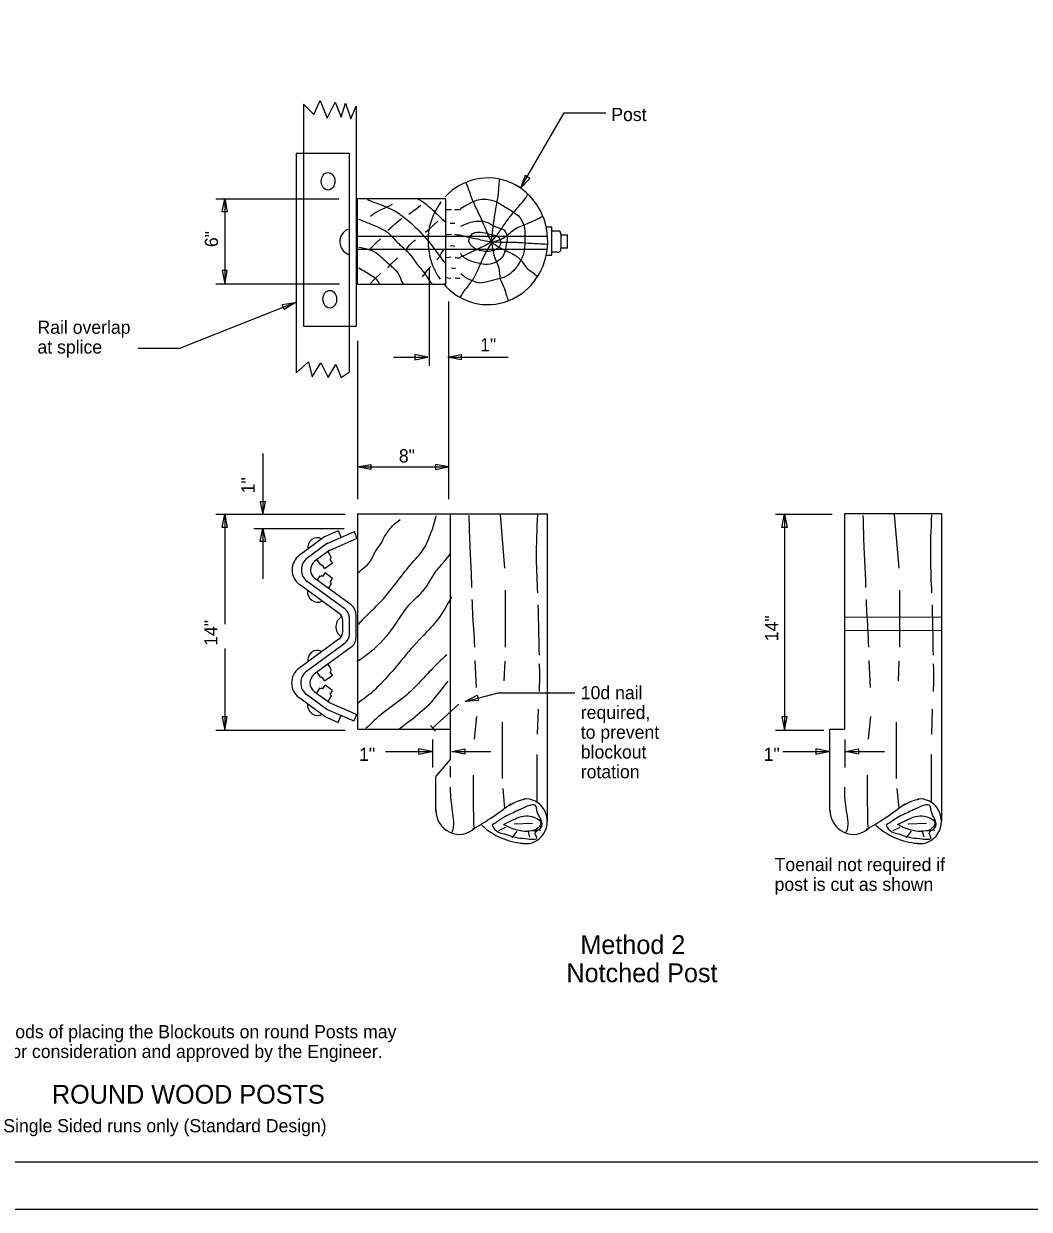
# Model space of a CAD drawing. Extents: x 0 to 34, y 0 to 22.
# Drawn here: x 8.69 to 19.37, y 0 to 12.6 of the extents above; entities that cross this region are included whole.
import ezdxf

# ---------------------------------------------------------------- set-up
doc = ezdxf.new("R2010")
doc.units = 0
for name, color, linetype in [('SH_Border', 7, 'Continuous'), ('SH_Cut_Line', 7, 'Continuous'), ('ST_Details', 7, 'Continuous'), ('ST_Text', 7, 'Continuous')]:
    doc.layers.add(name, color=color, linetype=linetype)

msp = doc.modelspace()

# ---------------------------------------------------------------- linework, layer by layer
at = {"layer": 'SH_Border'}
msp.add_lwpolyline([(1.5, 21.5), (33.5, 21.5), (33.5, 0.5), (1.5, 0.5)], close=True, dxfattribs=at)
at = {"layer": 'SH_Cut_Line'}
msp.add_lwpolyline([(0, 0), (34, 0), (34, 22), (0, 22)], close=True, dxfattribs=at)
at = {"layer": 'ST_Details'}
for p, q in [((11.658, 11.741), (11.658, 11.227)), ((12.218, 11.721), (12.218, 9.383)), ((11.583, 11.221), (11.583, 8.885)), ((11.583, 11.221), (12.143, 11.221)), ((11.658, 11.221), (11.658, 9.383)), ((12.143, 11.221), (12.143, 8.895)), ((12.232, 10.739), (13.171, 10.739)), ((12.232, 9.829), (12.232, 10.739)), ((13.17, 9.829), (13.17, 10.739)), ((13.216, 10.476), (13.266, 10.478)), ((12.225, 10.339), (14.248, 10.339)), ((13.174, 10.357), (13.23, 10.361)), ((14.239, 10.437), (14.299, 10.437)), ((14.251, 10.342), (14.251, 10.342)), ((14.299, 10.136), (14.299, 10.437)), ((14.299, 10.394), (14.367, 10.394)), ((14.393, 10.36), (14.394, 10.206)), ((14.393, 10.353), (14.464, 10.353)), ((14.464, 10.213), (14.464, 10.353)), ((14.394, 10.213), (14.464, 10.213)), ((12.225, 10.2), (14.248, 10.2)), ((13.174, 10.111), (13.228, 10.12)), ((14.239, 10.136), (14.299, 10.136)), ((14.299, 10.17), (14.358, 10.17)), ((12.232, 9.829), (13.17, 9.829)), ((13.17, 9.899), (13.226, 9.892)), ((11.658, 9.383), (12.143, 9.383)), ((12.143, 9.383), (12.218, 9.383)), ((12.232, 7.389), (12.232, 5.099)), ((12.232, 7.389), (14.252, 7.389)), ((13.218, 7.389), (13.218, 4.777)), ((13.748, 7.383), (13.795, 6.81)), ((14.252, 4.122), (14.252, 7.389)), ((17.405, 7.389), (17.405, 5.099)), ((18.439, 7.389), (17.405, 7.389)), ((17.935, 7.383), (17.982, 6.81)), ((18.439, 4.122), (18.439, 7.389)), ((11.887, 7.147), (12.031, 7.21)), ((11.912, 7.074), (12.201, 7.201)), ((12.059, 7.14), (12.031, 7.209)), ((12.227, 7.13), (12.2, 7.2)), ((11.887, 7.147), (11.614, 6.947)), ((11.914, 7.076), (11.684, 6.907)), ((11.941, 7.004), (12.231, 7.13)), ((11.94, 7.003), (11.773, 6.881)), ((11.951, 6.936), (11.921, 6.984)), ((11.835, 6.854), (11.806, 6.9)), ((11.884, 6.807), (11.861, 6.844)), ((11.884, 6.808), (11.966, 6.866)), ((11.966, 6.866), (11.943, 6.902)), ((12.164, 6.42), (11.78, 6.7)), ((11.805, 6.681), (11.837, 6.731)), ((11.865, 6.722), (11.89, 6.76)), ((11.969, 6.703), (11.89, 6.76)), ((11.944, 6.664), (11.968, 6.702)), ((12.038, 6.33), (11.615, 6.638)), ((12.101, 6.375), (11.697, 6.669)), ((11.923, 6.595), (11.954, 6.644)), ((13.803, 6.577), (13.803, 5.972)), ((17.989, 6.577), (17.989, 5.972)), ((12.218, 6.079), (12.218, 6.312)), ((12.076, 6.138), (12.076, 6.253)), ((12.147, 6.109), (12.147, 6.282)), ((12.147, 6.19), (12.147, 6.201)), ((17.405, 6.29), (18.44, 6.293)), ((12.038, 6.061), (11.608, 5.746)), ((17.405, 6.149), (18.439, 6.152)), ((12.101, 6.016), (11.69, 5.715)), ((12.165, 5.971), (11.773, 5.684)), ((13.479, 5.83), (13.492, 5.542)), ((13.798, 5.822), (13.789, 5.613)), ((17.666, 5.83), (17.678, 5.542)), ((17.984, 5.822), (17.975, 5.613)), ((11.835, 5.661), (11.806, 5.707)), ((11.884, 5.615), (11.966, 5.674)), ((11.951, 5.744), (11.921, 5.791)), ((11.966, 5.674), (11.943, 5.709)), ((11.884, 5.615), (11.861, 5.651)), ((11.865, 5.529), (11.89, 5.568)), ((11.969, 5.51), (11.89, 5.567)), ((11.888, 5.233), (11.608, 5.437)), ((11.908, 5.309), (11.691, 5.468)), ((11.931, 5.384), (11.773, 5.499)), ((11.805, 5.489), (11.837, 5.539)), ((11.923, 5.402), (11.954, 5.451)), ((11.944, 5.471), (11.968, 5.509)), ((12.196, 5.184), (11.907, 5.31)), ((11.931, 5.385), (12.224, 5.257)), ((12.629, 5.363), (12.629, 5.363)), ((12.994, 5.358), (12.846, 5.231)), ((13.029, 5.113), (13.309, 5.367)), ((14.151, 5.312), (14.143, 5.046)), ((18.338, 5.312), (18.33, 5.046)), ((11.885, 5.234), (12.029, 5.172)), ((12.028, 5.172), (12.057, 5.244)), ((12.195, 5.184), (12.224, 5.257)), ((13.497, 5.237), (13.472, 4.995)), ((13.769, 5.175), (13.769, 4.578)), ((17.684, 5.237), (17.659, 4.995)), ((17.956, 5.175), (17.956, 4.578)), ((12.232, 5.099), (13.224, 5.099)), ((13.06, 5.079), (13.009, 5.14)), ((17.25, 4.307), (17.25, 5.099)), ((17.25, 5.099), (17.405, 5.099)), ((13.218, 4.777), (13.07, 4.606)), ((13.218, 4.706), (13.218, 4.592)), ((13.064, 4.307), (13.064, 4.594)), ((13.07, 4.599), (13.07, 4.606)), ((13.776, 4.472), (13.796, 4.258)), ((17.963, 4.472), (17.983, 4.258)), ((13.064, 4.229), (13.064, 4.307)), ((17.25, 4.229), (17.25, 4.307)), ((13.736, 4.023), (13.81, 4.058)), ((13.897, 4.094), (14.092, 4.101)), ((14.179, 4.108), (14.173, 4.143)), ((17.922, 4.023), (17.996, 4.058)), ((18.083, 4.094), (18.278, 4.101)), ((18.366, 4.108), (18.36, 4.143)), ((13.877, 3.945), (13.93, 4.016)), ((14.065, 3.952), (14.045, 4.023)), ((14.18, 4.029), (14.099, 4.022)), ((14.099, 4.022), (14.139, 4.023)), ((18.063, 3.945), (18.117, 4.016)), ((18.251, 3.952), (18.231, 4.023)), ((18.366, 4.029), (18.286, 4.022)), ((18.286, 4.022), (18.325, 4.023))]:
    msp.add_line(p, q, dxfattribs=at)
for points in [[(11.658, 11.741), (11.77, 11.632), (11.836, 11.78), (11.91, 11.592), (11.994, 11.76), (12.06, 11.602), (12.106, 11.751), (12.162, 11.583), (12.218, 11.721)], [(12.372, 10.549), (12.418, 10.586), (12.478, 10.617), (12.552, 10.651), (12.604, 10.679)], [(12.779, 10.571), (12.833, 10.611), (12.867, 10.635), (12.904, 10.668)], [(12.556, 10.401), (12.598, 10.436), (12.635, 10.474), (12.687, 10.516), (12.708, 10.527)], [(12.955, 10.381), (12.998, 10.416), (13.042, 10.458), (13.088, 10.496)], [(12.37, 10.206), (12.397, 10.231), (12.435, 10.27), (12.478, 10.31)], [(12.752, 10.2), (12.783, 10.239), (12.825, 10.281), (12.85, 10.301)], [(12.552, 10.003), (12.593, 10.049), (12.658, 10.109)], [(13.076, 10.085), (13.103, 10.12), (13.126, 10.16), (13.153, 10.197)], [(12.923, 9.906), (12.952, 9.943), (12.978, 9.981), (13.009, 10.016)], [(12.359, 9.826), (12.422, 9.888), (12.478, 9.941)], [(11.583, 8.885), (11.714, 9.003), (11.752, 8.845), (11.845, 8.994), (11.92, 8.835), (12.004, 8.974), (12.06, 8.835), (12.143, 8.895)]]:
    msp.add_lwpolyline(points, dxfattribs=at)
for centre in [(11.92, 10.921), (11.938, 9.668)]:
    msp.add_ellipse(centre, major_axis=(0.0005, 0.0936), ratio=0.773782, dxfattribs=at)
for centre, major_axis, start_param, end_param in [((13.618, 10.284), (0, 0.673), 2.303639, 7.079119), ((13.618, 10.284), (0, 0.673), 0.900881, 2.214399), ((12.178, 10.279), (0, -0.141), 3.514867, 5.984065), ((14.364, 10.364), (0, 0.03), 4.574534, 6.237266), ((14.366, 10.365), (0, -0.0298), 1.431351, 1.439211), ((14.363, 10.201), (0, -0.0326), 6.093782, 8.002272), ((11.807, 7.028), (0, -0.107), 2.687211, 4.851441), ((11.715, 6.793), (0, -0.187), 3.747084, 5.680264), ((11.935, 6.924), (0, 0.0198), 3.70437, 5.352473), ((11.778, 6.793), (0, -0.15), 3.747137, 5.680324), ((11.84, 6.793), (0, -0.112), 3.747102, 5.680297), ((11.848, 6.865), (0, -0.0195), 5.247458, 6.879592), ((11.85, 6.708), (0, 0.021), 5.452301, 7.118326), ((11.81, 6.565), (0, -0.115), 4.640651, 6.714317), ((11.935, 6.646), (0, 0.021), 4.196406, 5.73538), ((11.988, 6.253), (0, 0.0937), 4.712389, 5.680377), ((12.041, 6.282), (0, 0.112), 4.712389, 5.68034), ((12.094, 6.312), (0, 0.131), 4.712389, 5.680267), ((12.117, 6.189), (0, -0.12), 3.613765, 5.74142), ((11.988, 6.138), (0, -0.0937), 0.605563, 1.570796), ((12.041, 6.109), (0, -0.112), 0.605651, 1.570796), ((12.094, 6.079), (0, -0.131), 0.605566, 1.570796), ((11.804, 5.831), (0, -0.107), 2.687211, 4.851441), ((11.709, 5.592), (0, -0.187), 3.747091, 5.68028), ((11.771, 5.592), (0, -0.15), 3.747115, 5.680355), ((11.833, 5.592), (0, -0.112), 3.747102, 5.680258), ((11.935, 5.731), (0, 0.0198), 3.70437, 5.352473), ((11.848, 5.672), (0, -0.0195), 5.247458, 6.879592), ((11.85, 5.515), (0, 0.021), 5.452301, 7.118326), ((11.935, 5.453), (0, 0.021), 4.196406, 5.73538), ((11.81, 5.362), (0, -0.115), 4.640651, 6.714317), ((14.097, 3.856), (0, 0.508), 0.179437, 0.530353), ((14.025, 4.122), (0, 0.237), 2.997307, 6.40595), ((18.284, 3.856), (0, 0.508), 0.179437, 0.530353), ((18.212, 4.122), (0, 0.237), 2.997307, 6.40595), ((13.313, 4.247), (0, -0.264), 4.726587, 7.018323), ((17.5, 4.247), (0, -0.264), 4.726587, 7.018323), ((14.039, 4.667), (0, -0.78), 5.564047, 6.222034), ((18.226, 4.667), (0, -0.78), 5.564047, 6.222034)]:
    msp.add_ellipse(centre, major_axis=major_axis, ratio=0.944544, start_param=start_param, end_param=end_param, dxfattribs=at)
for points in [[(13.654, 10.279), (13.617, 10.359), (13.573, 10.465), (13.527, 10.569), (13.479, 10.668), (13.435, 10.777), (13.422, 10.814), (13.385, 10.909)], [(13.656, 10.284), (13.667, 10.374), (13.683, 10.505), (13.704, 10.629), (13.729, 10.781), (13.738, 10.88), (13.744, 10.945)], [(12.337, 10.726), (12.439, 10.688), (12.629, 10.606), (12.779, 10.496), (12.923, 10.357), (13.057, 10.193), (13.153, 10.063), (13.173, 10.038)], [(12.867, 10.739), (12.961, 10.679), (13.09, 10.56), (13.171, 10.488)], [(13.328, 10.633), (13.395, 10.671), (13.514, 10.724), (13.658, 10.721), (13.823, 10.635), (13.942, 10.553), (13.999, 10.456), (14.011, 10.317), (14.003, 10.182), (13.959, 10.065), (13.892, 9.974), (13.811, 9.912), (13.706, 9.877), (13.596, 9.85), (13.514, 9.841), (13.45, 9.868), (13.399, 9.886), (13.349, 9.923), (13.33, 9.937)], [(13.658, 10.281), (13.706, 10.341), (13.777, 10.441), (13.842, 10.529), (13.928, 10.635), (13.972, 10.686), (14.02, 10.746), (14.042, 10.783)], [(13.174, 10.622), (13.224, 10.622), (13.23, 10.622)], [(13.262, 10.621), (13.301, 10.62), (13.326, 10.622)], [(12.243, 10.52), (12.422, 10.447), (12.535, 10.39), (12.671, 10.259), (12.771, 10.166), (12.89, 10.01), (12.973, 9.903), (13.021, 9.835), (13.03, 9.828)], [(13.33, 10.445), (13.397, 10.474), (13.472, 10.494), (13.606, 10.487), (13.702, 10.438), (13.786, 10.405), (13.823, 10.312), (13.813, 10.248), (13.792, 10.153), (13.719, 10.071), (13.614, 10.036), (13.481, 10.06), (13.399, 10.089), (13.351, 10.127), (13.328, 10.153)], [(13.66, 10.279), (13.779, 10.317), (13.898, 10.41), (14.04, 10.474), (14.122, 10.509), (14.201, 10.551)], [(13.262, 10.358), (13.289, 10.354), (13.328, 10.354)], [(13.654, 10.277), (13.577, 10.288), (13.506, 10.306), (13.414, 10.323), (13.356, 10.337), (13.335, 10.343)], [(13.414, 10.277), (13.429, 10.334), (13.462, 10.368), (13.541, 10.381), (13.637, 10.361), (13.733, 10.326), (13.754, 10.266), (13.702, 10.195), (13.631, 10.177), (13.546, 10.182), (13.481, 10.208), (13.437, 10.244), (13.418, 10.277)], [(12.248, 10.222), (12.426, 10.164), (12.512, 10.091), (12.618, 9.996), (12.677, 9.919), (12.712, 9.841), (12.723, 9.826)], [(13.221, 10.237), (13.239, 10.239), (13.268, 10.232)], [(13.66, 10.277), (13.614, 10.197), (13.587, 10.146), (13.539, 10.049), (13.518, 9.996), (13.46, 9.883), (13.439, 9.853), (13.418, 9.828), (13.389, 9.786), (13.36, 9.749), (13.341, 9.718), (13.328, 9.698), (13.322, 9.693)], [(13.654, 10.279), (13.61, 10.248), (13.543, 10.217), (13.435, 10.164), (13.358, 10.129), (13.328, 10.118)], [(13.654, 10.277), (13.769, 10.204), (13.898, 10.14), (13.988, 10.06), (14.053, 9.979), (14.095, 9.952), (14.132, 9.919), (14.149, 9.91)], [(13.658, 10.277), (13.827, 10.275), (13.984, 10.27), (14.114, 10.261), (14.199, 10.257), (14.249, 10.253)], [(13.658, 10.277), (13.673, 10.182), (13.696, 10.098), (13.733, 9.998), (13.75, 9.883), (13.792, 9.788), (13.815, 9.707), (13.836, 9.649)], [(13.269, 10.111), (13.27, 10.111), (13.32, 10.109), (13.326, 10.111)], [(12.246, 10), (12.382, 9.921), (12.433, 9.879), (12.468, 9.828)], [(13.232, 10.002), (13.257, 9.996), (13.274, 9.998)], [(13.27, 9.897), (13.31, 9.892), (13.324, 9.895)], [(12.233, 6.758), (12.302, 6.819), (12.368, 6.881), (12.419, 6.984), (12.48, 7.069), (12.52, 7.146), (12.56, 7.204), (12.604, 7.261), (12.687, 7.327)], [(12.237, 6.211), (12.335, 6.311), (12.488, 6.465), (12.662, 6.677), (12.815, 6.869), (12.945, 7.031), (12.989, 7.127), (13.025, 7.215), (13.068, 7.368)], [(13.416, 7.37), (13.427, 7.018), (13.44, 6.733), (13.444, 6.606)], [(14.144, 7.378), (14.132, 6.911), (14.144, 6.548)], [(17.602, 7.37), (17.613, 7.018), (17.627, 6.733), (17.631, 6.606)], [(18.33, 7.378), (18.319, 6.911), (18.331, 6.548)], [(12.226, 5.819), (12.379, 5.931), (12.618, 6.188), (12.789, 6.427), (12.942, 6.585), (13.058, 6.765), (13.163, 6.892), (13.219, 6.966)], [(13.23, 6.504), (13.082, 6.262), (12.887, 6.048), (12.672, 5.799), (12.477, 5.579), (12.336, 5.451), (12.228, 5.372)], [(13.449, 6.478), (13.453, 6.349), (13.474, 5.979), (13.474, 5.972)], [(17.635, 6.478), (17.64, 6.349), (17.66, 5.979), (17.66, 5.972)], [(14.149, 6.42), (14.152, 6.328), (14.161, 5.887)], [(18.336, 6.42), (18.339, 6.328), (18.347, 5.887)], [(13.183, 5.892), (13.048, 5.764), (12.9, 5.607), (12.732, 5.444), (12.504, 5.273), (12.323, 5.108)], [(14.163, 5.795), (14.166, 5.638), (14.161, 5.5)], [(18.349, 5.795), (18.352, 5.638), (18.347, 5.5)], [(12.994, 5.358), (13.051, 5.427), (13.197, 5.611)], [(12.673, 5.1), (12.782, 5.185), (12.846, 5.231)], [(14.139, 4.833), (14.139, 4.62), (14.139, 4.371), (14.139, 4.328)], [(18.326, 4.833), (18.326, 4.62), (18.326, 4.371), (18.326, 4.328)], [(13.46, 4.613), (13.46, 4.443), (13.467, 4.058)], [(17.647, 4.613), (17.647, 4.443), (17.653, 4.058)], [(13.218, 4.485), (13.218, 4.464), (13.238, 4.229), (13.238, 4.009), (13.232, 3.994)], [(17.405, 4.485), (17.405, 4.464), (17.425, 4.229), (17.425, 4.009), (17.418, 3.994)], [(13.453, 4.037), (13.641, 4.151), (13.86, 4.307)], [(13.662, 4.08), (13.816, 4.179), (13.951, 4.243), (14.132, 4.279), (14.139, 4.235), (14.18, 4.143), (14.18, 4.051), (14.119, 3.994), (14.139, 3.952), (14.018, 3.938), (13.91, 3.952), (13.796, 3.987), (13.722, 4.009), (13.662, 4.08)], [(17.64, 4.037), (17.828, 4.151), (18.046, 4.307)], [(17.848, 4.08), (18.003, 4.179), (18.137, 4.243), (18.319, 4.279), (18.326, 4.235), (18.366, 4.143), (18.366, 4.051), (18.306, 3.994), (18.325, 3.952), (18.204, 3.938), (18.097, 3.952), (17.983, 3.987), (17.909, 4.009), (17.848, 4.08)], [(13.783, 4.087), (13.87, 4.13), (13.951, 4.165), (14.045, 4.179), (14.125, 4.158), (14.179, 4.108), (14.152, 4.051), (14.065, 4.016), (13.951, 4.023), (13.877, 4.044), (13.789, 4.087)], [(17.969, 4.087), (18.057, 4.13), (18.137, 4.165), (18.231, 4.179), (18.312, 4.158), (18.366, 4.108), (18.339, 4.051), (18.251, 4.016), (18.137, 4.023), (18.063, 4.044), (17.976, 4.087)]]:
    msp.add_spline(points, degree=3, dxfattribs=at)
at = {"layer": 'ST_Text'}
for p, q in [((10.727, 10.736), (12.033, 10.736)), ((10.822, 10.736), (10.822, 10.159)), ((10.822, 10.159), (10.822, 9.832)), ((12.993, 9.995), (12.993, 8.96)), ((10.727, 9.832), (12.042, 9.832)), ((13.2, 9.644), (13.2, 7.969)), ((12.232, 9.227), (12.232, 7.969)), ((12.616, 9.054), (12.981, 9.054)), ((13.194, 9.054), (13.835, 9.054)), ((11.228, 8.03), (11.228, 7.377)), ((12.232, 7.969), (12.232, 7.544)), ((13.2, 7.969), (13.2, 7.544)), ((12.233, 7.886), (13.2, 7.886)), ((10.727, 7.384), (12.101, 7.384)), ((10.822, 7.384), (10.822, 6.217)), ((16.674, 7.384), (17.274, 7.384)), ((16.769, 7.384), (16.769, 6.217)), ((11.133, 7.234), (12.091, 7.234)), ((11.228, 7.234), (11.228, 6.698)), ((16.769, 6.217), (16.769, 5.959)), ((10.822, 5.959), (10.822, 5.09)), ((16.769, 5.959), (16.769, 5.09)), ((13.376, 5.395), (13.726, 5.488)), ((13.726, 5.488), (14.54, 5.488)), ((10.727, 5.09), (11.826, 5.09)), ((11.826, 5.09), (12.101, 5.09)), ((16.674, 5.09), (16.999, 5.09)), ((16.999, 5.09), (17.188, 5.09)), ((13.028, 4.991), (13.028, 4.694)), ((17.411, 4.991), (17.411, 4.694)), ((12.532, 4.864), (13.021, 4.864)), ((13.234, 4.864), (13.649, 4.864)), ((16.751, 4.864), (17.241, 4.864)), ((17.416, 4.864), (17.83, 4.864))]:
    msp.add_line(p, q, dxfattribs=at)
for points in [[(13.965, 10.848), (14.43, 11.647), (14.87, 11.647)], [(11.575, 9.635), (10.342, 9.145), (9.902, 9.145)]]:
    msp.add_lwpolyline(points, dxfattribs=at)
for points in [[(14.015, 10.982), (13.965, 10.848), (14.063, 10.952)], [(10.794, 10.596), (10.822, 10.736), (10.85, 10.596)], [(10.794, 9.972), (10.822, 9.832), (10.85, 9.972)], [(11.434, 9.611), (11.575, 9.635), (11.454, 9.559)], [(12.841, 9.026), (12.981, 9.054), (12.841, 9.082)], [(13.334, 9.026), (13.194, 9.054), (13.334, 9.082)], [(12.373, 7.858), (12.233, 7.886), (12.373, 7.914)], [(13.06, 7.858), (13.2, 7.886), (13.06, 7.914)], [(11.2, 7.517), (11.228, 7.377), (11.256, 7.517)], [(10.794, 7.244), (10.822, 7.384), (10.85, 7.244)], [(16.741, 7.244), (16.769, 7.384), (16.797, 7.244)], [(11.2, 7.094), (11.228, 7.234), (11.256, 7.094)], [(13.518, 5.407), (13.376, 5.395), (13.503, 5.461)], [(10.794, 5.23), (10.822, 5.09), (10.85, 5.23)], [(16.741, 5.23), (16.769, 5.09), (16.797, 5.23)], [(12.881, 4.836), (13.021, 4.864), (12.881, 4.892)], [(13.374, 4.836), (13.234, 4.864), (13.374, 4.892)], [(17.101, 4.836), (17.241, 4.864), (17.101, 4.892)], [(17.556, 4.836), (17.416, 4.864), (17.556, 4.892)]]:
    msp.add_lwpolyline(points, close=True, dxfattribs=at)

# ---------------------------------------------------------------- texts
for s, height, p in [('Post', 0.14, (14.929, 11.561)), ('Rail overlap', 0.14, (8.833, 9.301)), ('at splice', 0.14, (8.833, 9.091)), ('1"', 0.14, (13.536, 9.113)), ('8" ', 0.14, (12.672, 7.934)), ('10d nail ', 0.14, (14.605, 5.419)), ('required, ', 0.14, (14.605, 5.209)), ('to prevent ', 0.14, (14.605, 4.999)), ('blockout ', 0.14, (14.605, 4.789)), ('1"', 0.14, (12.25, 4.764)), ('1" ', 0.14, (16.548, 4.764)), ('rotation', 0.14, (14.605, 4.579)), ('Toenail not required if', 0.14, (16.664, 3.593)), ('post is cut as shown', 0.14, (16.664, 3.383)), ('  Method 2', 0.2, (14.452, 2.712)), ('Notched Post', 0.2, (14.452, 2.412)), ('Alternate methods of placing the Blockouts on round Posts may', 0.14, (7.38, 1.817)), ('be submitted for consideration and approved by the Engineer.', 0.14, (7.38, 1.607)), ('ROUND WOOD POSTS', 0.2, (8.987, 1.122)), ('Single Sided runs only (Standard Design)', 0.14, (8.47, 0.818))]:
    msp.add_text(s, height=height, dxfattribs=at).set_placement(p)
for s, p in [('6" ', (10.751, 10.222)), ('1" ', (11.14, 7.606)), ('14" ', (16.702, 6.035)), ('14" ', (10.744, 5.986))]:
    msp.add_text(s, height=0.14, rotation=90, dxfattribs=at).set_placement(p)

doc.saveas('drawing.dxf')
